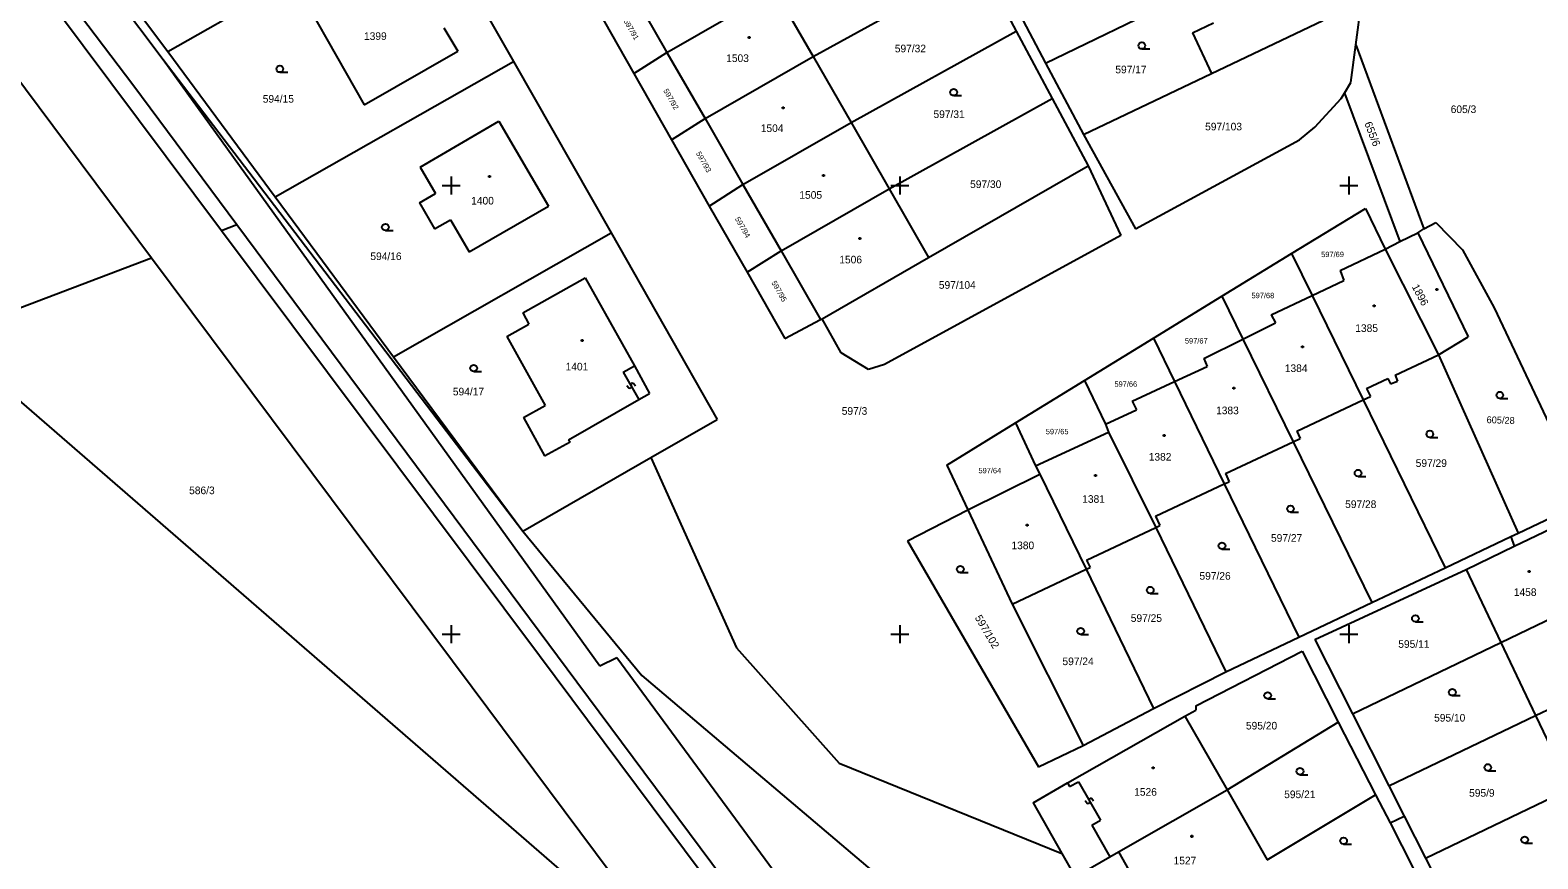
# Model space of a CAD drawing. Extents: x -493648 to -493033, y -1127718 to -1127026.
# Drawn here: x -493296.9 to -493128.9, y -1127275 to -1127182.7 of the extents above; entities that cross this region are included whole.
import ezdxf

# ---------------------------------------------------------------- set-up
doc = ezdxf.new("R2010")
doc.units = 0
doc.layers.add('katastrální mapa', color=7, linetype='Continuous')
doc.layers.add('síť', color=7, linetype='Continuous')

msp = doc.modelspace()

# ---------------------------------------------------------------- linework, layer by layer
at = {"layer": 'katastrální mapa'}
for p, q in [((-493320.1, -1127135.31), (-493282.06, -1127185.95)), ((-493323.39, -1127138.67), (-493285.46, -1127188.73)), ((-493292.95, -1127169.69), (-493281.56, -1127185.07)), ((-493281.56, -1127185.07), (-493252.96, -1127168.78)), ((-493209.67, -1127185.62), (-493191.04, -1127175.31)), ((-493191.04, -1127175.31), (-493187.04, -1127182.81)), ((-493247.62, -1127178.16), (-493243.06, -1127186.16)), ((-493230.45, -1127177.34), (-493225.95, -1127185.16)), ((-493225.95, -1127185.16), (-493213.92, -1127178.24)), ((-493213.92, -1127178.24), (-493209.67, -1127185.62)), ((-493187.99, -1127178.39), (-493183.77, -1127186.36)), ((-493294.06, -1127180.27), (-493275.56, -1127205.01)), ((-493265.85, -1127180.16), (-493259.67, -1127190.99)), ((-493233.85, -1127180.12), (-493229.65, -1127187.51)), ((-493183.77, -1127186.36), (-493169.18, -1127179.27)), ((-493149.22, -1127184.31), (-493148.59, -1127179.57)), ((-493167.42, -1127182.97), (-493165.08, -1127181.86)), ((-493165.27, -1127187.52), (-493152.88, -1127181.62)), ((-493250.8, -1127182.41), (-493249.25, -1127185.04)), ((-493216.85, -1127183.41), (-493216.7, -1127183.41)), ((-493216.85, -1127183.56), (-493216.85, -1127183.41)), ((-493216.7, -1127183.56), (-493216.85, -1127183.56)), ((-493216.7, -1127183.41), (-493216.7, -1127183.56)), ((-493205.44, -1127192.97), (-493187.04, -1127182.81)), ((-493187.04, -1127182.81), (-493183.04, -1127190.31)), ((-493167.42, -1127182.97), (-493165.27, -1127187.52)), ((-493300.59, -1127184.98), (-493283.37, -1127208.04)), ((-493281.56, -1127185.07), (-493269.58, -1127201.26)), ((-493259.67, -1127190.99), (-493249.25, -1127185.04)), ((-493229.65, -1127187.51), (-493225.95, -1127185.16)), ((-493225.95, -1127185.16), (-493221.7, -1127192.54)), ((-493173.05, -1127184.78), (-493172.17, -1127184.78)), ((-493149.77, -1127188.51), (-493149.22, -1127184.31)), ((-493149.22, -1127184.31), (-493141.62, -1127204.83)), ((-493282.06, -1127185.95), (-493242.02, -1127238.5)), ((-493282.06, -1127185.95), (-493233.42, -1127253.5)), ((-493269.58, -1127201.26), (-493243.06, -1127186.16)), ((-493243.06, -1127186.16), (-493232.17, -1127205.27)), ((-493221.7, -1127192.54), (-493209.67, -1127185.62)), ((-493209.67, -1127185.62), (-493205.44, -1127192.97)), ((-493183.77, -1127186.36), (-493179.56, -1127194.32)), ((-493285.46, -1127188.73), (-493273.85, -1127204.35)), ((-493269.07, -1127187.38), (-493268.19, -1127187.38)), ((-493229.65, -1127187.51), (-493225.44, -1127194.89)), ((-493179.56, -1127194.32), (-493165.27, -1127187.52)), ((-493150.49, -1127189.71), (-493149.77, -1127188.51)), ((-493201.19, -1127200.37), (-493183.04, -1127190.31)), ((-493194.01, -1127189.98), (-493193.13, -1127189.98)), ((-493183.04, -1127190.31), (-493179.04, -1127197.8)), ((-493153.79, -1127193.48), (-493150.86, -1127190.31)), ((-493150.86, -1127190.31), (-493150.49, -1127189.71)), ((-493150.49, -1127189.71), (-493144.3, -1127206.24)), ((-493213.07, -1127191.25), (-493212.92, -1127191.25)), ((-493213.07, -1127191.4), (-493213.07, -1127191.25)), ((-493212.92, -1127191.4), (-493213.07, -1127191.4)), ((-493212.92, -1127191.25), (-493212.92, -1127191.4)), ((-493253.46, -1127197.94), (-493244.67, -1127192.81)), ((-493244.67, -1127192.81), (-493239.14, -1127202.28)), ((-493225.44, -1127194.89), (-493221.7, -1127192.54)), ((-493221.7, -1127192.54), (-493217.48, -1127199.89)), ((-493217.48, -1127199.89), (-493205.44, -1127192.97)), ((-493205.44, -1127192.97), (-493201.19, -1127200.37)), ((-493155.5, -1127194.89), (-493153.79, -1127193.48)), ((-493225.44, -1127194.89), (-493221.24, -1127202.28)), ((-493179.56, -1127194.32), (-493173.76, -1127204.81)), ((-493173.76, -1127204.81), (-493155.5, -1127194.89)), ((-493253.46, -1127197.94), (-493251.74, -1127200.9)), ((-493208.59, -1127198.81), (-493208.44, -1127198.81)), ((-493208.59, -1127198.96), (-493208.59, -1127198.81)), ((-493208.44, -1127198.81), (-493208.44, -1127198.96)), ((-493196.8, -1127208.01), (-493179.04, -1127197.8)), ((-493179.04, -1127197.8), (-493175.39, -1127205.55)), ((-493245.79, -1127198.92), (-493245.64, -1127198.92)), ((-493245.79, -1127199.07), (-493245.79, -1127198.92)), ((-493245.64, -1127199.07), (-493245.79, -1127199.07)), ((-493245.64, -1127198.92), (-493245.64, -1127199.07)), ((-493221.24, -1127202.28), (-493217.48, -1127199.89)), ((-493217.48, -1127199.89), (-493213.22, -1127207.29)), ((-493213.22, -1127207.29), (-493201.19, -1127200.37)), ((-493208.44, -1127198.96), (-493208.59, -1127198.96)), ((-493201.19, -1127200.37), (-493196.8, -1127208.01)), ((-493269.58, -1127201.26), (-493256.4, -1127219.07)), ((-493253.52, -1127201.93), (-493251.74, -1127200.9)), ((-493253.52, -1127201.93), (-493251.83, -1127204.83)), ((-493251.83, -1127204.83), (-493250.06, -1127203.8)), ((-493250.06, -1127203.8), (-493247.97, -1127207.4)), ((-493247.97, -1127207.4), (-493239.14, -1127202.28)), ((-493221.24, -1127202.28), (-493217.03, -1127209.66)), ((-493156.38, -1127207.57), (-493148.14, -1127202.57)), ((-493148.14, -1127202.57), (-493145.93, -1127207.1)), ((-493275.56, -1127205.01), (-493273.85, -1127204.35)), ((-493275.56, -1127205.01), (-493240.14, -1127252.38)), ((-493273.85, -1127204.35), (-493235.98, -1127255.31)), ((-493257.32, -1127205.01), (-493256.44, -1127205.01)), ((-493256.4, -1127219.07), (-493232.17, -1127205.27)), ((-493232.17, -1127205.27), (-493220.34, -1127226.05)), ((-493175.39, -1127205.55), (-493201.71, -1127219.92)), ((-493144.3, -1127206.24), (-493142.3, -1127205.28)), ((-493142.3, -1127205.28), (-493141.62, -1127204.83)), ((-493142.3, -1127205.28), (-493136.71, -1127216.85)), ((-493141.62, -1127204.83), (-493140.29, -1127204.12)), ((-493140.29, -1127204.12), (-493137.33, -1127207.17)), ((-493204.53, -1127205.81), (-493204.38, -1127205.81)), ((-493204.53, -1127205.96), (-493204.53, -1127205.81)), ((-493204.38, -1127205.96), (-493204.53, -1127205.96)), ((-493204.38, -1127205.81), (-493204.38, -1127205.96)), ((-493150.96, -1127209.47), (-493145.93, -1127207.1)), ((-493145.93, -1127207.1), (-493144.3, -1127206.24)), ((-493145.93, -1127207.1), (-493140, -1127218.85)), ((-493137.33, -1127207.17), (-493133.79, -1127213.61)), ((-493299.89, -1127214.33), (-493283.37, -1127208.04)), ((-493283.37, -1127208.04), (-493247.64, -1127255.9)), ((-493217.03, -1127209.66), (-493213.22, -1127207.29)), ((-493213.22, -1127207.29), (-493208.83, -1127214.93)), ((-493208.67, -1127214.84), (-493196.8, -1127208.01)), ((-493164.12, -1127212.31), (-493156.38, -1127207.57)), ((-493156.38, -1127207.57), (-493154.09, -1127212.24)), ((-493242.02, -1127214.19), (-493235.05, -1127210.29)), ((-493235.05, -1127210.29), (-493229.58, -1127220.07)), ((-493217.03, -1127209.66), (-493212.83, -1127217.04)), ((-493154.09, -1127212.24), (-493150.54, -1127210.56)), ((-493150.96, -1127209.47), (-493150.54, -1127210.56)), ((-493171.75, -1127217.01), (-493164.12, -1127212.31)), ((-493164.12, -1127212.31), (-493161.78, -1127217.1)), ((-493158.63, -1127214.39), (-493154.09, -1127212.24)), ((-493154.09, -1127212.24), (-493148.39, -1127223.89)), ((-493140.27, -1127211.5), (-493140.12, -1127211.5)), ((-493140.27, -1127211.65), (-493140.27, -1127211.5)), ((-493140.12, -1127211.65), (-493140.27, -1127211.65)), ((-493140.12, -1127211.5), (-493140.12, -1127211.65)), ((-493147.25, -1127213.32), (-493147.1, -1127213.32)), ((-493147.25, -1127213.47), (-493147.25, -1127213.32)), ((-493147.1, -1127213.47), (-493147.25, -1127213.47)), ((-493147.1, -1127213.32), (-493147.1, -1127213.47)), ((-493133.79, -1127213.61), (-493123.64, -1127235.17)), ((-493243.79, -1127216.83), (-493241.32, -1127215.45)), ((-493242.02, -1127214.19), (-493241.32, -1127215.45)), ((-493212.83, -1127217.04), (-493208.83, -1127214.93)), ((-493208.83, -1127214.93), (-493208.67, -1127214.84)), ((-493206.54, -1127218.65), (-493208.67, -1127214.84)), ((-493161.78, -1127217.1), (-493158.14, -1127215.31)), ((-493158.63, -1127214.39), (-493158.14, -1127215.31)), ((-493243.79, -1127216.83), (-493239.5, -1127224.5)), ((-493235.47, -1127217.18), (-493235.32, -1127217.18)), ((-493235.47, -1127217.33), (-493235.47, -1127217.18)), ((-493235.32, -1127217.33), (-493235.47, -1127217.33)), ((-493235.32, -1127217.18), (-493235.32, -1127217.33)), ((-493179.43, -1127221.72), (-493171.75, -1127217.01)), ((-493171.75, -1127217.01), (-493169.4, -1127221.84)), ((-493166.15, -1127219.26), (-493161.78, -1127217.1)), ((-493161.78, -1127217.1), (-493156.19, -1127228.54)), ((-493140, -1127218.85), (-493136.71, -1127216.85)), ((-493203.49, -1127220.5), (-493206.54, -1127218.65)), ((-493155.24, -1127217.91), (-493155.09, -1127217.91)), ((-493155.24, -1127218.06), (-493155.24, -1127217.91)), ((-493155.09, -1127218.06), (-493155.24, -1127218.06)), ((-493155.09, -1127217.91), (-493155.09, -1127218.06)), ((-493144.84, -1127221.12), (-493140, -1127218.85)), ((-493140, -1127218.85), (-493131.12, -1127238.72)), ((-493256.4, -1127219.07), (-493242.02, -1127238.5)), ((-493247.48, -1127220.72), (-493246.6, -1127220.72)), ((-493230.81, -1127220.8), (-493229.58, -1127220.07)), ((-493229.58, -1127220.07), (-493227.91, -1127223.17)), ((-493201.71, -1127219.92), (-493203.49, -1127220.5)), ((-493169.4, -1127221.84), (-493165.78, -1127220.17)), ((-493166.15, -1127219.26), (-493165.78, -1127220.17)), ((-493300.83, -1127221.6), (-493222.53, -1127289.56)), ((-493230.81, -1127220.8), (-493229.08, -1127223.84)), ((-493230.2, -1127222.58), (-493230.42, -1127222.3)), ((-493229.91, -1127222.07), (-493229.95, -1127222.21)), ((-493229.95, -1127222.21), (-493229.94, -1127222.43)), ((-493229.83, -1127222.02), (-493229.91, -1127222.07)), ((-493229.69, -1127222.06), (-493229.83, -1127222.02)), ((-493229.47, -1127222.34), (-493229.69, -1127222.06)), ((-493187.13, -1127226.45), (-493179.43, -1127221.72)), ((-493179.43, -1127221.72), (-493177.08, -1127226.57)), ((-493174.14, -1127224.03), (-493169.4, -1127221.84)), ((-493169.4, -1127221.84), (-493163.86, -1127233.25)), ((-493148.01, -1127222.61), (-493145.64, -1127221.49)), ((-493145.64, -1127221.49), (-493145.36, -1127222.1)), ((-493145.36, -1127222.1), (-493144.56, -1127221.81)), ((-493144.84, -1127221.12), (-493144.56, -1127221.81)), ((-493236.93, -1127228.32), (-493229.08, -1127223.84)), ((-493230.06, -1127222.62), (-493230.2, -1127222.58)), ((-493229.98, -1127222.57), (-493230.06, -1127222.62)), ((-493229.94, -1127222.43), (-493229.98, -1127222.57)), ((-493229.08, -1127223.84), (-493227.91, -1127223.17)), ((-493174.14, -1127224.03), (-493173.65, -1127224.98)), ((-493162.87, -1127222.49), (-493162.72, -1127222.49)), ((-493162.87, -1127222.64), (-493162.87, -1127222.49)), ((-493162.72, -1127222.64), (-493162.87, -1127222.64)), ((-493162.72, -1127222.49), (-493162.72, -1127222.64)), ((-493155.8, -1127227.36), (-493148.39, -1127223.89)), ((-493148.39, -1127223.89), (-493147.59, -1127223.52)), ((-493148.39, -1127223.89), (-493139.25, -1127242.58)), ((-493148.01, -1127222.61), (-493147.59, -1127223.52)), ((-493133.17, -1127223.72), (-493132.29, -1127223.72)), ((-493241.92, -1127225.85), (-493239.5, -1127224.5)), ((-493177.08, -1127226.57), (-493173.65, -1127224.98)), ((-493241.92, -1127225.85), (-493239.61, -1127230.13)), ((-493227.75, -1127230.31), (-493220.34, -1127226.05)), ((-493194.78, -1127231.16), (-493187.13, -1127226.45)), ((-493187.13, -1127226.45), (-493184.91, -1127231.24)), ((-493177.08, -1127226.57), (-493176.76, -1127227.46)), ((-493155.8, -1127227.36), (-493155.42, -1127228.18)), ((-493239.61, -1127230.13), (-493236.74, -1127228.56)), ((-493236.93, -1127228.32), (-493236.74, -1127228.56)), ((-493184.91, -1127231.24), (-493176.76, -1127227.46)), ((-493176.76, -1127227.46), (-493171.49, -1127238.09)), ((-493170.63, -1127227.78), (-493170.48, -1127227.78)), ((-493170.63, -1127227.93), (-493170.63, -1127227.78)), ((-493170.48, -1127227.93), (-493170.63, -1127227.93)), ((-493170.48, -1127227.78), (-493170.48, -1127227.93)), ((-493163.74, -1127232.08), (-493156.19, -1127228.54)), ((-493156.19, -1127228.54), (-493155.42, -1127228.18)), ((-493156.19, -1127228.54), (-493147.43, -1127246.47)), ((-493140.97, -1127228.06), (-493140.09, -1127228.06)), ((-493242.02, -1127238.5), (-493227.75, -1127230.31)), ((-493227.75, -1127230.31), (-493218.22, -1127251.52)), ((-493194.78, -1127231.16), (-493192.42, -1127236.15)), ((-493192.42, -1127236.15), (-493184.41, -1127232.17)), ((-493184.91, -1127231.24), (-493184.41, -1127232.17)), ((-493184.41, -1127232.17), (-493179.24, -1127242.76)), ((-493178.27, -1127232.24), (-493178.12, -1127232.24)), ((-493178.27, -1127232.39), (-493178.27, -1127232.24)), ((-493178.12, -1127232.39), (-493178.27, -1127232.39)), ((-493178.12, -1127232.24), (-493178.12, -1127232.39)), ((-493163.74, -1127232.08), (-493163.32, -1127233)), ((-493148.96, -1127232.41), (-493148.08, -1127232.41)), ((-493171.53, -1127236.85), (-493163.86, -1127233.25)), ((-493163.86, -1127233.25), (-493163.32, -1127233)), ((-493163.86, -1127233.25), (-493155.56, -1127250.33)), ((-493131.12, -1127238.72), (-493123.64, -1127235.17)), ((-493199.15, -1127239.57), (-493192.42, -1127236.15)), ((-493192.42, -1127236.15), (-493187.5, -1127246.66)), ((-493171.53, -1127236.85), (-493171.05, -1127237.88)), ((-493156.48, -1127236.4), (-493155.6, -1127236.4)), ((-493242.02, -1127238.5), (-493228.76, -1127254.59)), ((-493185.9, -1127237.76), (-493185.75, -1127237.76)), ((-493185.9, -1127237.91), (-493185.9, -1127237.76)), ((-493185.75, -1127237.91), (-493185.9, -1127237.91)), ((-493185.75, -1127237.76), (-493185.75, -1127237.91)), ((-493179.22, -1127241.73), (-493171.49, -1127238.09)), ((-493171.49, -1127238.09), (-493171.05, -1127237.88)), ((-493171.49, -1127238.09), (-493163.69, -1127254.19)), ((-493139.25, -1127242.58), (-493131.96, -1127239.12)), ((-493131.96, -1127239.12), (-493131.12, -1127238.72)), ((-493131.96, -1127239.12), (-493131.56, -1127240.19)), ((-493131.56, -1127240.19), (-493127.44, -1127238.2)), ((-493199.15, -1127239.57), (-493184.57, -1127264.78)), ((-493164.12, -1127240.52), (-493163.24, -1127240.52)), ((-493136.93, -1127242.78), (-493131.56, -1127240.19)), ((-493179.22, -1127241.73), (-493178.82, -1127242.57)), ((-493193.27, -1127243.13), (-493192.39, -1127243.13)), ((-493187.5, -1127246.66), (-493179.24, -1127242.76)), ((-493179.24, -1127242.76), (-493178.82, -1127242.57)), ((-493179.24, -1127242.76), (-493171.75, -1127258.28)), ((-493153.76, -1127250.6), (-493136.93, -1127242.78)), ((-493147.43, -1127246.47), (-493139.25, -1127242.58)), ((-493136.93, -1127242.78), (-493133.05, -1127250.93)), ((-493129.99, -1127242.94), (-493129.84, -1127242.94)), ((-493129.99, -1127243.09), (-493129.99, -1127242.94)), ((-493129.84, -1127243.09), (-493129.99, -1127243.09)), ((-493129.84, -1127242.94), (-493129.84, -1127243.09)), ((-493172.11, -1127245.45), (-493171.23, -1127245.45)), ((-493187.5, -1127246.66), (-493179.6, -1127262.4)), ((-493155.56, -1127250.33), (-493147.43, -1127246.47)), ((-493133.05, -1127250.93), (-493123.57, -1127246.34)), ((-493142.57, -1127248.62), (-493141.69, -1127248.62)), ((-493179.86, -1127250.03), (-493178.98, -1127250.03)), ((-493163.69, -1127254.19), (-493155.56, -1127250.33)), ((-493153.76, -1127250.6), (-493149.58, -1127258.86)), ((-493149.58, -1127258.86), (-493133.05, -1127250.93)), ((-493133.05, -1127250.93), (-493129.18, -1127259.06)), ((-493240.14, -1127252.38), (-493202.62, -1127302.64)), ((-493233.42, -1127253.5), (-493231.53, -1127252.6)), ((-493231.53, -1127252.6), (-493198.67, -1127297.24)), ((-493218.22, -1127251.52), (-493206.77, -1127264.35)), ((-493167.05, -1127257.98), (-493155.2, -1127251.87)), ((-493155.2, -1127251.87), (-493151.19, -1127259.8)), ((-493171.75, -1127258.28), (-493163.69, -1127254.19)), ((-493247.64, -1127255.9), (-493222.53, -1127289.56)), ((-493235.98, -1127255.31), (-493202.36, -1127300.42)), ((-493228.76, -1127254.59), (-493183.29, -1127293.12)), ((-493129.18, -1127259.06), (-493119.69, -1127254.49)), ((-493159.03, -1127257.19), (-493158.15, -1127257.19)), ((-493138.46, -1127256.84), (-493137.58, -1127256.84)), ((-493181.33, -1127266.55), (-493168.27, -1127259.12)), ((-493179.6, -1127262.4), (-493171.75, -1127258.28)), ((-493168.27, -1127259.12), (-493167.04, -1127258.45)), ((-493168.27, -1127259.12), (-493163.53, -1127267.35)), ((-493167.05, -1127257.98), (-493167.04, -1127258.45)), ((-493149.58, -1127258.86), (-493145.52, -1127266.89)), ((-493145.52, -1127266.89), (-493129.18, -1127259.06)), ((-493129.18, -1127259.06), (-493125.31, -1127267.2)), ((-493163.53, -1127267.35), (-493151.19, -1127259.8)), ((-493151.19, -1127259.8), (-493147, -1127267.88)), ((-493184.57, -1127264.78), (-493179.6, -1127262.4)), ((-493206.77, -1127264.35), (-493181.95, -1127274.42)), ((-493171.86, -1127264.79), (-493171.71, -1127264.79)), ((-493171.86, -1127264.94), (-493171.86, -1127264.79)), ((-493171.71, -1127264.94), (-493171.86, -1127264.94)), ((-493171.71, -1127264.79), (-493171.71, -1127264.94)), ((-493155.43, -1127265.65), (-493154.55, -1127265.65)), ((-493134.51, -1127265.21), (-493133.63, -1127265.21)), ((-493185.17, -1127268.79), (-493181.33, -1127266.55)), ((-493181.33, -1127266.55), (-493181.1, -1127266.98)), ((-493181.1, -1127266.98), (-493180.11, -1127266.43)), ((-493180.11, -1127266.43), (-493177.67, -1127270.73)), ((-493175.66, -1127274.25), (-493163.53, -1127267.35)), ((-493163.53, -1127267.35), (-493159.1, -1127275.12)), ((-493145.52, -1127266.89), (-493143.82, -1127270.26)), ((-493141.46, -1127274.93), (-493125.31, -1127267.2)), ((-493185.17, -1127268.79), (-493181.95, -1127274.42)), ((-493179.15, -1127268.84), (-493179.36, -1127268.56)), ((-493179.01, -1127268.88), (-493179.15, -1127268.84)), ((-493178.92, -1127268.83), (-493179.01, -1127268.88)), ((-493178.88, -1127268.69), (-493178.92, -1127268.83)), ((-493178.86, -1127268.33), (-493178.9, -1127268.47)), ((-493178.9, -1127268.47), (-493178.88, -1127268.69)), ((-493178.77, -1127268.28), (-493178.86, -1127268.33)), ((-493178.63, -1127268.32), (-493178.77, -1127268.28)), ((-493178.42, -1127268.6), (-493178.63, -1127268.32)), ((-493159.1, -1127275.12), (-493147, -1127267.88)), ((-493147, -1127267.88), (-493145.4, -1127271.02)), ((-493178.63, -1127271.27), (-493177.67, -1127270.73)), ((-493145.4, -1127271.02), (-493143.82, -1127270.26)), ((-493145.4, -1127271.02), (-493142.8, -1127276.12)), ((-493143.82, -1127270.26), (-493141.46, -1127274.93)), ((-493178.63, -1127271.27), (-493176.62, -1127274.8)), ((-493167.54, -1127272.44), (-493167.39, -1127272.44)), ((-493167.54, -1127272.59), (-493167.54, -1127272.44)), ((-493167.39, -1127272.59), (-493167.54, -1127272.59)), ((-493167.39, -1127272.44), (-493167.39, -1127272.59)), ((-493181.95, -1127274.42), (-493180.46, -1127277.01)), ((-493176.62, -1127274.8), (-493175.66, -1127274.25)), ((-493175.66, -1127274.25), (-493173.34, -1127278.33)), ((-493150.57, -1127273.39), (-493149.69, -1127273.39)), ((-493130.4, -1127273.28), (-493129.52, -1127273.28)), ((-493180.46, -1127277.01), (-493176.62, -1127274.8)), ((-493141.46, -1127274.93), (-493137.4, -1127282.96))]:
    msp.add_line(p, q, dxfattribs=at)
for centre in [(-493173.05, -1127184.405), (-493269.07, -1127187.005), (-493194.01, -1127189.605), (-493257.32, -1127204.635), (-493247.48, -1127220.345), (-493133.17, -1127223.345), (-493140.97, -1127227.685), (-493148.96, -1127232.035), (-493156.48, -1127236.025), (-493164.12, -1127240.145), (-493193.27, -1127242.755), (-493172.11, -1127245.075), (-493142.57, -1127248.245), (-493179.86, -1127249.655), (-493159.03, -1127256.815), (-493138.46, -1127256.465), (-493155.43, -1127265.275), (-493134.51, -1127264.835), (-493150.57, -1127273.015), (-493130.4, -1127272.905)]:
    msp.add_circle(centre, 0.375, dxfattribs=at)
at = {"layer": 'síť'}
for p, q in [((-493251, -1127200), (-493249, -1127200)), ((-493250, -1127199), (-493250, -1127201)), ((-493201, -1127200), (-493199, -1127200)), ((-493200, -1127199), (-493200, -1127201)), ((-493151, -1127200), (-493149, -1127200)), ((-493150, -1127199), (-493150, -1127201)), ((-493250, -1127249), (-493250, -1127251)), ((-493200, -1127249), (-493200, -1127251)), ((-493150, -1127249), (-493150, -1127251)), ((-493251, -1127250), (-493249, -1127250)), ((-493201, -1127250), (-493199, -1127250)), ((-493151, -1127250), (-493149, -1127250))]:
    msp.add_line(p, q, dxfattribs=at)

# ---------------------------------------------------------------- texts
at = {"layer": 'katastrální mapa'}
for s, height, rotation, p in [('597/91', 0.599994, 299.772, (-493230.82, -1127181.65)), ('597/92', 0.599994, 299.772, (-493226.38, -1127189.42)), ('655/6', 0.849996, 291.1229972, (-493148.27, -1127193.07)), ('597/93', 0.599994, 299.772, (-493222.74, -1127196.41)), ('597/94', 0.599994, 299.772, (-493218.4, -1127203.7)), ('597/95', 0.599994, 299.772, (-493214.34, -1127210.82)), ('1896', 0.849996, 298.0529972, (-493143, -1127211.26)), ('605/28', 0.764994, 358.1949583, (-493134.65, -1127226.47)), ('597/102', 0.849996, 300.519, (-493191.69, -1127248.15))]:
    msp.add_text(s, height=height, rotation=rotation, dxfattribs=at).set_placement(p)
for s, height, p in [('1399', 0.849996, (-493259.7, -1127183.77)), ('1503', 0.849996, (-493219.35, -1127186.23)), ('597/32', 0.849996, (-493200.57, -1127185.15)), ('597/17', 0.849996, (-493176, -1127187.49)), ('594/15', 0.849996, (-493270.98, -1127190.76)), ('597/31', 0.849996, (-493196.26, -1127192.47)), ('605/3', 0.849996, (-493138.64, -1127191.92)), ('1504', 0.849996, (-493215.5, -1127194.03)), ('597/103', 0.849996, (-493166, -1127193.85)), ('597/30', 0.849996, (-493192.18, -1127200.27)), ('1400', 0.849996, (-493247.76, -1127202.11)), ('1505', 0.849996, (-493211.2, -1127201.47)), ('594/16', 0.849996, (-493258.99, -1127208.3)), ('1506', 0.849996, (-493206.75, -1127208.67)), ('597/69', 0.599994, (-493153.07, -1127207.97)), ('597/104', 0.849996, (-493195.66, -1127211.5)), ('597/68', 0.599994, (-493160.83, -1127212.55)), ('1385', 0.849996, (-493149.27, -1127216.31)), ('597/67', 0.599994, (-493168.25, -1127217.6)), ('1401', 0.849996, (-493237.24, -1127220.6)), ('1384', 0.849996, (-493157.12, -1127220.78)), ('597/66', 0.599994, (-493176.1, -1127222.42)), ('594/17', 0.849996, (-493249.8, -1127223.38)), ('597/3', 0.849996, (-493206.48, -1127225.54)), ('1383', 0.849996, (-493164.78, -1127225.48)), ('597/65', 0.599994, (-493183.75, -1127227.71)), ('1382', 0.849996, (-493172.28, -1127230.65)), ('597/29', 0.849996, (-493142.54, -1127231.35)), ('597/64', 0.599994, (-493191.25, -1127232.06)), ('586/3', 0.849996, (-493279.18, -1127234.39)), ('1381', 0.849996, (-493179.69, -1127235.35)), ('597/28', 0.849996, (-493150.4, -1127235.93)), ('597/27', 0.849996, (-493158.66, -1127239.69)), ('1380', 0.849996, (-493187.57, -1127240.52)), ('597/26', 0.849996, (-493166.63, -1127243.92)), ('1458', 0.849996, (-493131.61, -1127245.73)), ('597/25', 0.849996, (-493174.28, -1127248.62)), ('595/11', 0.849996, (-493144.48, -1127251.51)), ('597/24', 0.849996, (-493181.89, -1127253.44)), ('595/10', 0.849996, (-493140.49, -1127259.73)), ('595/20', 0.849996, (-493161.45, -1127260.61)), ('1526', 0.849996, (-493173.9, -1127267.99)), ('595/21', 0.849996, (-493157.19, -1127268.26)), ('595/9', 0.849996, (-493136.59, -1127268.1)), ('1527', 0.849996, (-493169.51, -1127275.64))]:
    msp.add_text(s, height=height, dxfattribs=at).set_placement(p)

doc.saveas('drawing.dxf')
